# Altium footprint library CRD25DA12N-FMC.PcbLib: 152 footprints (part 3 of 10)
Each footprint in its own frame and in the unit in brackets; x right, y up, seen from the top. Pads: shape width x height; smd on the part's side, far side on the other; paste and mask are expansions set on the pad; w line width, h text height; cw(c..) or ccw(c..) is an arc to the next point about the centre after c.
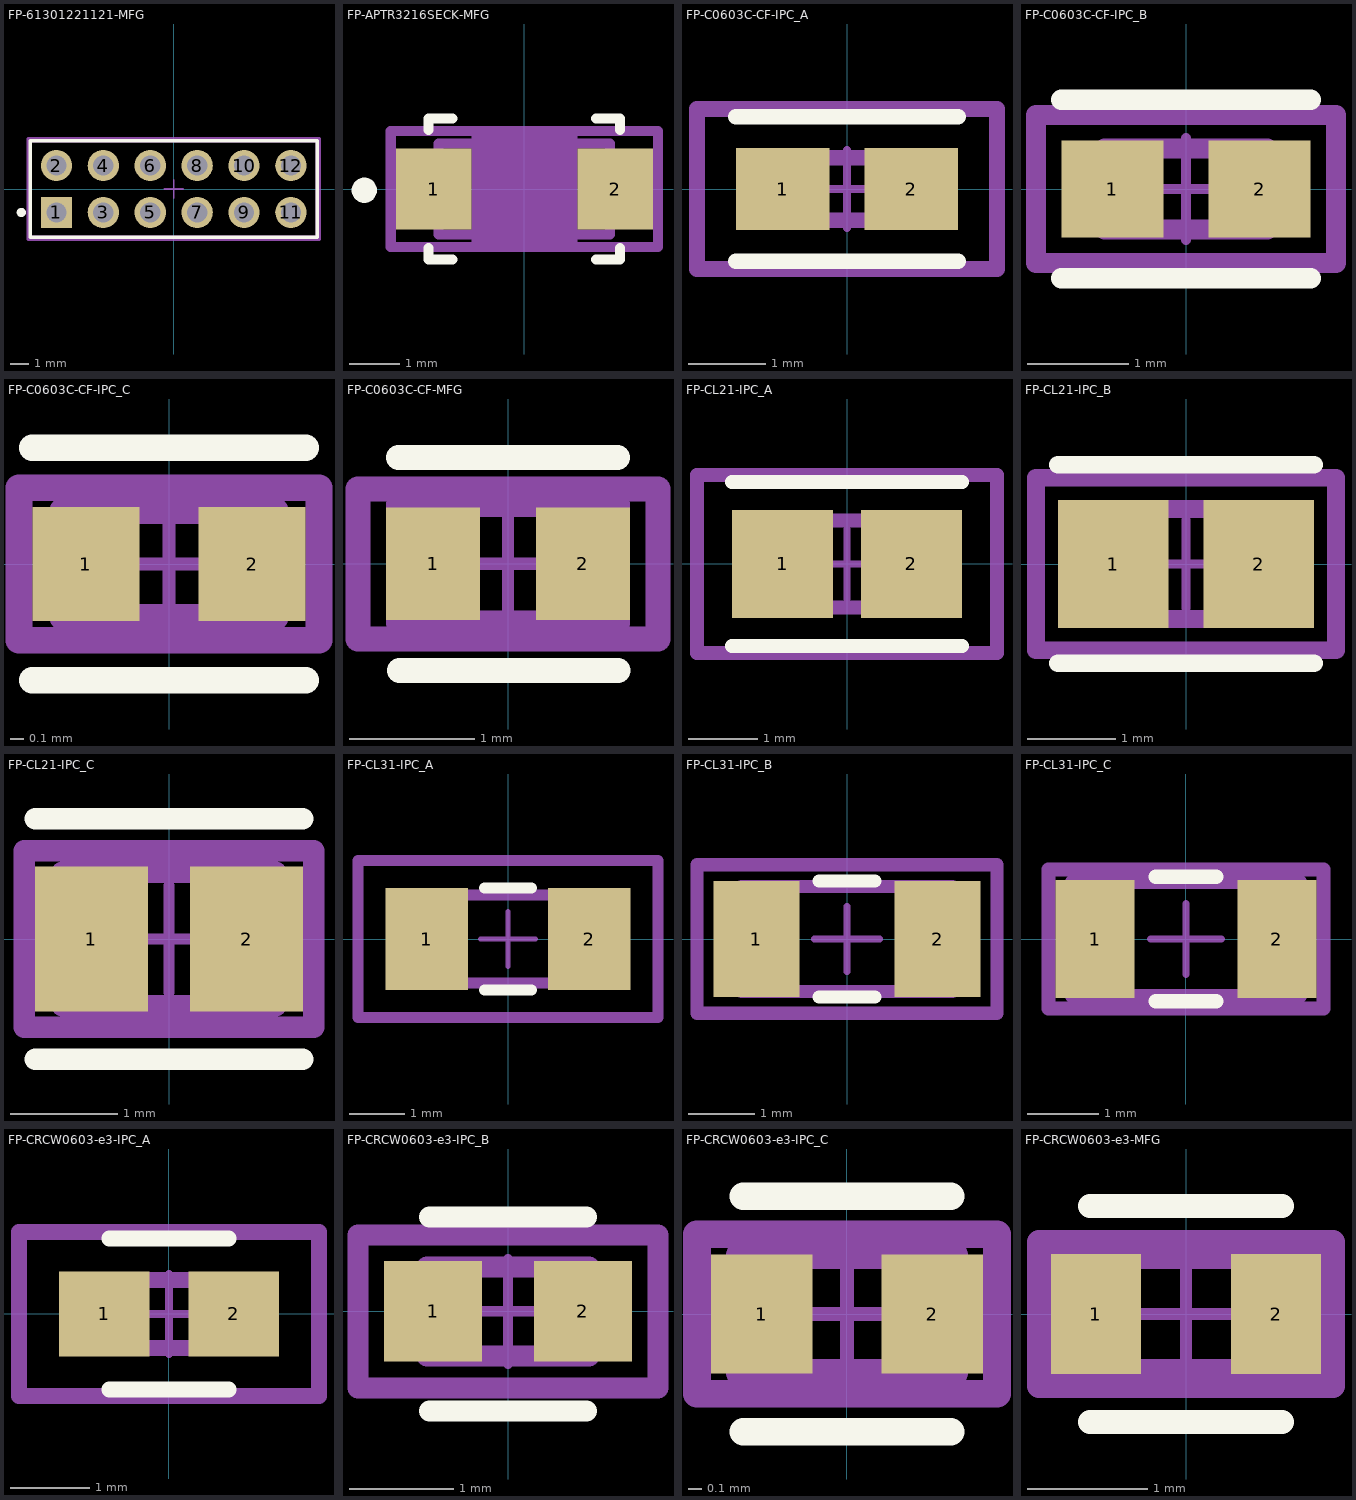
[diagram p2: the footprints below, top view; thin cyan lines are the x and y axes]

## FP-61301221121-MFG [mm]
pads (12):
  rect 1.7x1.7 hole 1.1 paste-2539.97 mask+0: 1(-6.35,-1.27)
  round 1.7 hole 1.1 paste-2539.97 mask+0: 2(-6.35,1.27) 3(-3.81,-1.27) 4(-3.81,1.27) 5(-1.27,-1.27) 6(-1.27,1.27) 7(1.27,-1.27) 8(1.27,1.27) 9(3.81,-1.27) 10(3.81,1.27) 11(6.35,-1.27) 12(6.35,1.27)
Top Overlay:
  circle w0.25: c-8.255,-1.27 r0.125
  lines w0.2: -7.77,-2.615 7.77,-2.615 7.77,2.615 -7.77,2.615 -7.77,-2.615
Mechanical 5:
  lines w0.2: -7.87,-2.715 7.87,-2.715 7.87,2.715 -7.87,2.715 -7.87,-2.715
  text ".Designator" at 0,0.188 h1
Mechanical 13:
  lines w0.2: -7.77,-2.615 7.77,-2.615 7.77,2.615 -7.77,2.615 -7.77,-2.615
Mechanical 15:
  lines w0.2: -7.87,-2.715 7.87,-2.715 7.87,2.715 -7.87,2.715 -7.87,-2.715
Mechanical 16:
  lines w0.1: -0.5,0 0.5,0 ; 0,-0.5 0,0.5
3D body "Conn_Wurth_Electronics_61301221121_eec.STEP": height 0.25, standoff 0, extent -7.87,-2.715 7.87,2.715

## FP-APTR3216SECK-MFG [mm]
pads (2):
  rect 1.5x1.6 smd paste+0 mask+0: 1(-1.8,0) 2(1.8,0)
Top Overlay:
  circle w0.25: c-3.175,-0.025 r0.125
  lines w0.2: -1.9,-1.175 -1.9,-1.4 -1.425,-1.4 ; -1.9,1.175 -1.9,1.4 -1.425,1.4 ; 1.425,-1.4 1.9,-1.4 1.9,-1.175 ; 1.425,1.4 1.9,1.4 1.9,1.175
Bottom 3D Body:
  rectangle: -1.05,-1.15 1.05,1.15
Mechanical 5:
  lines w0.2: -2.65,-1.15 -2.65,1.15 2.65,1.15 2.65,-1.15 -2.65,-1.15
  text ".Designator" at 0,0 h1
Mechanical 13:
  lines w0.2: -1.7,-0.9 -1.7,0.9 1.7,0.9 1.7,-0.9 -1.7,-0.9
Mechanical 15:
  lines w0.2: -2.65,-1.15 -2.65,1.15 2.65,1.15 2.65,-1.15 -2.65,-1.15
Mechanical 16:
  lines w0.1: -0.5,0 0.5,0 ; 0,-0.5 0,0.5
3D body "LED 1206 - PURPLE.STEP": height 1.1, standoff 0, extent -1.6,-0.8 1.6,0.802

## FP-C0603C-CF-IPC_A [mil]
pads (2):
  rect 47.5x41.66 smd paste+0 mask+0: 1(-32.51,0) 2(32.51,0)
Top Overlay:
  lines w7.87: -56.26,-36.58 56.26,-36.58 ; -56.26,36.58 56.26,36.58
Mechanical 5:
  lines w7.87: -75.95,-40.52 -75.95,40.52 75.95,40.52 75.95,-40.52 -75.95,-40.52
  text ".Designator" at 0,7.4 h39.37
Mechanical 13:
  lines w7.87: -31.5,-15.75 -31.5,15.75 31.5,15.75 31.5,-15.75 -31.5,-15.75
Mechanical 15:
  lines w7.87: -75.95,-40.52 -75.95,40.52 75.95,40.52 75.95,-40.52 -75.95,-40.52
Mechanical 16:
  lines w3.94: -19.68,0 19.68,0 ; 0,-19.68 0,19.68
3D body "Cap_KEMET_C0603C272M5JACTU_eec.STEP": height 10, standoff 0, extent -75.95,-40.52 75.95,40.52

## FP-C0603C-CF-IPC_B [mm]
pads (2):
  rect 1.007x0.958 smd paste+0 mask+0: 1(-0.726,0) 2(0.726,0)
Top Overlay:
  lines w0.2: -1.229,-0.879 1.229,-0.879 ; -1.229,0.879 1.229,0.879
Mechanical 5:
  lines w0.2: -1.479,-0.729 -1.479,0.729 1.479,0.729 1.479,-0.729 -1.479,-0.729
  text ".Designator" at 0,0.188 h1
Mechanical 13:
  lines w0.2: -0.8,-0.4 -0.8,0.4 0.8,0.4 0.8,-0.4 -0.8,-0.4
Mechanical 15:
  lines w0.2: -1.479,-0.729 -1.479,0.729 1.479,0.729 1.479,-0.729 -1.479,-0.729
Mechanical 16:
  lines w0.1: -0.5,0 0.5,0 ; 0,-0.5 0,0.5
3D body "Cap_KEMET_C0603C272M5JACTU_eec.STEP": height 0.25, standoff 0, extent -1.479,-0.729 1.479,0.729

## FP-C0603C-CF-IPC_C [mm]
pads (2):
  rect 0.807x0.858 smd paste+0 mask+0: 1(-0.626,0) 2(0.626,0)
Top Overlay:
  lines w0.2: -1.029,-0.875 1.029,-0.875 ; -1.029,0.875 1.029,0.875
Mechanical 5:
  lines w0.2: -1.129,-0.575 1.129,-0.575 1.129,0.575 -1.129,0.575 -1.129,-0.575
  text ".Designator" at 0,0.188 h1
Mechanical 13:
  lines w0.2: -0.8,-0.4 0.8,-0.4 0.8,0.4 -0.8,0.4 -0.8,-0.4
Mechanical 15:
  lines w0.2: -1.129,-0.575 1.129,-0.575 1.129,0.575 -1.129,0.575 -1.129,-0.575
Mechanical 16:
  lines w0.1: -0.5,0 0.5,0 ; 0,-0.5 0,0.5
3D body "Cap_KEMET_C0603C272M5JACTU_eec.STEP": height 0.25, standoff 0, extent -1.129,-0.575 1.129,0.575

## FP-C0603C-CF-MFG [mm]
pads (2):
  rect 0.75x0.9 smd paste+0 mask+0: 1(-0.6,0) 2(0.6,0)
Top Overlay:
  lines w0.2: -0.875,0.85 0.875,0.85 ; -0.87,-0.853 0.88,-0.853
Mechanical 5:
  lines w0.2: -1.2,-0.6 1.2,-0.6 1.2,0.6 -1.2,0.6 -1.2,-0.6
  text ".Designator" at 0,0.188 h1
Mechanical 13:
  lines w0.2: -0.875,-0.475 0.875,-0.475 0.875,0.475 -0.875,0.475 -0.875,-0.475
Mechanical 15:
  lines w0.2: -1.2,-0.6 1.2,-0.6 1.2,0.6 -1.2,0.6 -1.2,-0.6
Mechanical 16:
  lines w0.1: -0.5,0 0.5,0 ; 0,-0.5 0,0.5
3D body "Cap_KEMET_C0603C272M5JACTU_eec.STEP": height 0.25, standoff 0, extent -1.2,-0.6 1.2,0.6

## FP-CL21-IPC_A [mm]
pads (2):
  rect 1.455x1.556 smd paste+0 mask+0: 1(-0.926,0) 2(0.926,0)
Top Overlay:
  lines w0.2: -1.653,-1.178 1.653,-1.178 ; -1.653,1.178 1.653,1.178
Mechanical 5:
  lines w0.2: -2.153,-1.278 -2.153,1.278 2.153,1.278 2.153,-1.278 -2.153,-1.278
  text ".Designator" at 0,0.188 h1
Mechanical 13:
  lines w0.2: -1,-0.625 -1,0.625 1,0.625 1,-0.625 -1,-0.625
Mechanical 15:
  lines w0.2: -2.153,-1.278 -2.153,1.278 2.153,1.278 2.153,-1.278 -2.153,-1.278
Mechanical 16:
  lines w0.1: -0.5,0 0.5,0 ; 0,-0.5 0,0.5
3D body "Cap_Samsung_CL21B273KBANNNC_eec.STEP": height 0.25, standoff 0, extent -2.153,-1.278 2.153,1.278

## FP-CL21-IPC_B [mm]
pads (2):
  rect 1.255x1.456 smd paste+0 mask+0: 1(-0.826,0) 2(0.826,0)
Top Overlay:
  lines w0.2: -1.453,-1.128 1.453,-1.128 ; -1.453,1.128 1.453,1.128
Mechanical 5:
  lines w0.2: -1.703,-0.978 -1.703,0.978 1.703,0.978 1.703,-0.978 -1.703,-0.978
  text ".Designator" at 0,0.188 h1
Mechanical 13:
  lines w0.2: -1,-0.625 -1,0.625 1,0.625 1,-0.625 -1,-0.625
Mechanical 15:
  lines w0.2: -1.703,-0.978 -1.703,0.978 1.703,0.978 1.703,-0.978 -1.703,-0.978
Mechanical 16:
  lines w0.1: -0.5,0 0.5,0 ; 0,-0.5 0,0.5
3D body "Cap_Samsung_CL21B273KBANNNC_eec.STEP": height 0.25, standoff 0, extent -1.703,-0.978 1.703,0.978

## FP-CL21-IPC_C [mm]
pads (2):
  rect 1.055x1.356 smd paste+0 mask+0: 1(-0.726,0) 2(0.726,0)
Top Overlay:
  lines w0.2: -1.253,-1.125 1.253,-1.125 ; -1.253,1.125 1.253,1.125
Mechanical 5:
  lines w0.2: -1.353,-0.825 -1.353,0.825 1.353,0.825 1.353,-0.825 -1.353,-0.825
  text ".Designator" at 0,0.188 h1
Mechanical 13:
  lines w0.2: -1,-0.625 -1,0.625 1,0.625 1,-0.625 -1,-0.625
Mechanical 15:
  lines w0.2: -1.353,-0.825 -1.353,0.825 1.353,0.825 1.353,-0.825 -1.353,-0.825
Mechanical 16:
  lines w0.1: -0.5,0 0.5,0 ; 0,-0.5 0,0.5
3D body "Cap_Samsung_CL21B273KBANNNC_eec.STEP": height 0.25, standoff 0, extent -1.353,-0.825 1.353,0.825

## FP-CL31-IPC_A [mm]
pads (2):
  rect 1.505x1.858 smd paste+0 mask+0: 1(-1.476,0) 2(1.476,0)
Top Overlay:
  lines w0.2: -0.424,-0.929 0.424,-0.929 ; -0.424,0.929 0.424,0.929
Mechanical 5:
  lines w0.2: -2.729,-1.429 -2.729,1.429 2.729,1.429 2.729,-1.429 -2.729,-1.429
  text ".Designator" at 0,0.188 h1
Mechanical 13:
  lines w0.2: -1.6,-0.8 -1.6,0.8 1.6,0.8 1.6,-0.8 -1.6,-0.8
Mechanical 15:
  lines w0.2: -2.729,-1.429 -2.729,1.429 2.729,1.429 2.729,-1.429 -2.729,-1.429
Mechanical 16:
  lines w0.1: -0.5,0 0.5,0 ; 0,-0.5 0,0.5
3D body "Cap_Samsung_CL31B105KOFNNNE_eec.STEP": height 0.25, standoff 0, extent -2.729,-1.429 2.729,1.429

## FP-CL31-IPC_B [mm]
pads (2):
  rect 1.305x1.758 smd paste+0 mask+0: 1(-1.376,0) 2(1.376,0)
Top Overlay:
  lines w0.2: -0.424,-0.879 0.424,-0.879 ; -0.424,0.879 0.424,0.879
Mechanical 5:
  lines w0.2: -2.279,-1.129 -2.279,1.129 2.279,1.129 2.279,-1.129 -2.279,-1.129
  text ".Designator" at 0,0.188 h1
Mechanical 13:
  lines w0.2: -1.6,-0.8 -1.6,0.8 1.6,0.8 1.6,-0.8 -1.6,-0.8
Mechanical 15:
  lines w0.2: -2.279,-1.129 -2.279,1.129 2.279,1.129 2.279,-1.129 -2.279,-1.129
Mechanical 16:
  lines w0.1: -0.5,0 0.5,0 ; 0,-0.5 0,0.5
3D body "Cap_Samsung_CL31B105KOFNNNE_eec.STEP": height 0.25, standoff 0, extent -2.279,-1.129 2.279,1.129

## FP-CL31-IPC_C [mm]
pads (2):
  rect 1.105x1.658 smd paste+0 mask+0: 1(-1.276,0) 2(1.276,0)
Top Overlay:
  lines w0.2: -0.424,-0.875 0.424,-0.875 ; -0.424,0.875 0.424,0.875
Mechanical 5:
  lines w0.2: -1.929,-0.975 -1.929,0.975 1.929,0.975 1.929,-0.975 -1.929,-0.975
  text ".Designator" at 0,0.188 h1
Mechanical 13:
  lines w0.2: -1.6,-0.8 -1.6,0.8 1.6,0.8 1.6,-0.8 -1.6,-0.8
Mechanical 15:
  lines w0.2: -1.929,-0.975 -1.929,0.975 1.929,0.975 1.929,-0.975 -1.929,-0.975
Mechanical 16:
  lines w0.1: -0.5,0 0.5,0 ; 0,-0.5 0,0.5
3D body "Cap_Samsung_CL31B105KOFNNNE_eec.STEP": height 0.25, standoff 0, extent -1.929,-0.975 1.929,0.975

## FP-CRCW0603-e3-IPC_A [mm]
pads (2):
  rect 1.135x1.062 smd paste+0 mask+0: 1(-0.815,0) 2(0.815,0)
Top Overlay:
  lines w0.2: -0.75,-0.95 0.75,-0.95 ; -0.75,0.95 0.75,0.95
Mechanical 5:
  lines w0.2: -1.883,-1.031 1.883,-1.031 1.883,1.031 -1.883,1.031 -1.883,-1.031
  text ".Designator" at 0,0.188 h1
Mechanical 13:
  lines w0.2: -0.775,-0.425 0.775,-0.425 0.775,0.425 -0.775,0.425 -0.775,-0.425
Mechanical 15:
  lines w0.2: -1.883,-1.031 1.883,-1.031 1.883,1.031 -1.883,1.031 -1.883,-1.031
Mechanical 16:
  lines w0.1: -0.5,0 0.5,0 ; 0,-0.5 0,0.5
3D body "Res_Vishay_CRCW06033M90FKEC_eec.STEP": height 0.25, standoff 0, extent -1.883,-1.031 1.883,1.031

## FP-CRCW0603-e3-IPC_B [mm]
pads (2):
  rect 0.935x0.962 smd paste+0 mask+0: 1(-0.715,0) 2(0.715,0)
Top Overlay:
  lines w0.2: -0.75,-0.95 0.75,-0.95 ; -0.75,0.9 0.75,0.9
Mechanical 5:
  lines w0.2: -1.433,-0.731 -1.433,0.731 1.433,0.731 1.433,-0.731 -1.433,-0.731
  text ".Designator" at 0,0.188 h1
Mechanical 13:
  lines w0.2: -0.775,-0.425 -0.775,0.425 0.775,0.425 0.775,-0.425 -0.775,-0.425
Mechanical 15:
  lines w0.2: -1.433,-0.731 -1.433,0.731 1.433,0.731 1.433,-0.731 -1.433,-0.731
Mechanical 16:
  lines w0.1: -0.5,0 0.5,0 ; 0,-0.5 0,0.5
3D body "Res_Vishay_CRCW06033M90FKEC_eec.STEP": height 0.25, standoff 0, extent -1.433,-0.731 1.433,0.731

## FP-CRCW0603-e3-IPC_C [mm]
pads (2):
  rect 0.735x0.862 smd paste+0 mask+0: 1(-0.615,0) 2(0.615,0)
Top Overlay:
  lines w0.2: -0.75,-0.85 0.75,-0.85 ; -0.75,0.85 0.75,0.85
Mechanical 5:
  lines w0.2: -1.083,-0.575 1.083,-0.575 1.083,0.575 -1.083,0.575 -1.083,-0.575
  text ".Designator" at 0,0.188 h1
Mechanical 13:
  lines w0.2: -0.775,-0.425 0.775,-0.425 0.775,0.425 -0.775,0.425 -0.775,-0.425
Mechanical 15:
  lines w0.2: -1.083,-0.575 1.083,-0.575 1.083,0.575 -1.083,0.575 -1.083,-0.575
Mechanical 16:
  lines w0.1: -0.5,0 0.5,0 ; 0,-0.5 0,0.5
3D body "Res_Vishay_CRCW06033M90FKEC_eec.STEP": height 0.25, standoff 0, extent -1.083,-0.575 1.083,0.575

## FP-CRCW0603-e3-MFG [mm]
pads (2):
  rect 0.75x1 smd paste+0 mask+0: 1(-0.75,0) 2(0.75,0)
Top Overlay:
  lines w0.2: -0.8,-0.9 0.8,-0.9 ; -0.8,0.9 0.8,0.9
Mechanical 5:
  lines w0.2: -1.225,-0.6 1.225,-0.6 1.225,0.6 -1.225,0.6 -1.225,-0.6
  text ".Designator" at 0,0.188 h1
Mechanical 13:
  lines w0.2: -0.825,-0.475 0.825,-0.475 0.825,0.475 -0.825,0.475 -0.825,-0.475
Mechanical 15:
  lines w0.2: -1.225,-0.6 1.225,-0.6 1.225,0.6 -1.225,0.6 -1.225,-0.6
Mechanical 16:
  lines w0.1: -0.5,0 0.5,0 ; 0,-0.5 0,0.5
3D body "Res_Vishay_CRCW06033M90FKEC_eec.STEP": height 0.25, standoff 0, extent -1.225,-0.6 1.225,0.6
